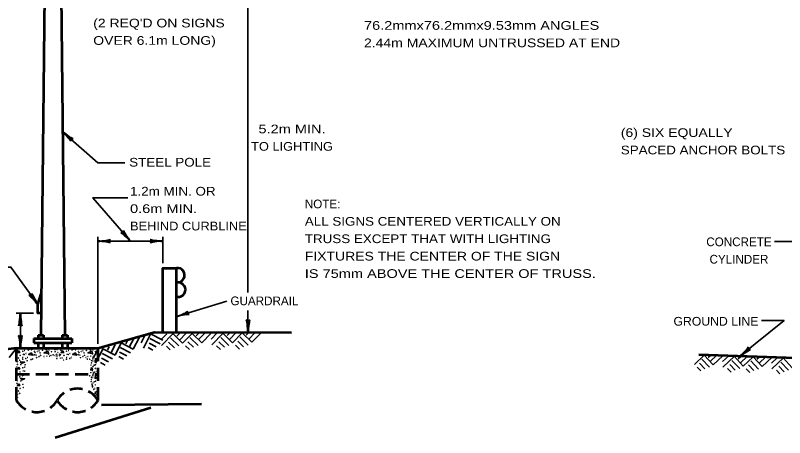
# Model space of a CAD drawing. Extents: x -31 to 824, y -13 to 531.
# Drawn here: x 91.3 to 303.3, y 278.2 to 394.6 of the extents above; entities that cross this region are included whole.
import ezdxf
from ezdxf.enums import TextEntityAlignment as Align

# ---------------------------------------------------------------- set-up
doc = ezdxf.new("R2010")
doc.units = 0
doc.header["$LTSCALE"] = 1.2
doc.linetypes.add('MEDIUM_DASHED', pattern=[4.5, 3, -1.5])
doc.layers.add('1', color=7, linetype='Continuous', lineweight=35)

msp = doc.modelspace()

# ---------------------------------------------------------------- linework, layer by layer
at = {"layer": '1', "lineweight": 53}
for p, q in [((99.754, 448.994), (98.27, 306.494)), ((103.648, 423.794), (104.87, 306.494)), ((135.713, 307.45), (135.713, 324.988)), ((96.32, 305.594), (106.82, 305.594)), ((96.32, 305.594), (96.32, 304.394)), ((97.52, 306.494), (99.02, 306.494)), ((97.52, 306.494), (97.52, 305.594)), ((99.02, 306.494), (99.02, 305.594)), ((104.12, 306.494), (105.62, 306.494)), ((104.12, 306.494), (104.12, 305.594)), ((105.62, 306.494), (105.62, 305.594)), ((106.82, 305.594), (106.82, 304.394)), ((96.32, 304.394), (106.82, 304.394)), ((97.52, 304.394), (97.52, 302.894)), ((99.02, 304.394), (99.02, 302.894)), ((104.12, 304.394), (104.12, 302.894)), ((105.62, 304.394), (105.62, 302.894)), ((91.52, 302.894), (67.699, 299.97)), ((91.52, 302.894), (114.02, 302.894)), ((313.283, 299.881), (279.704, 301.053)), ((102.244, 278.229), (128.57, 286.517)), ((114.96, 287.265), (142.559, 287.541))]:
    msp.add_line(p, q, dxfattribs=at)
at = {"layer": '1'}
for p, q in [((155.379, 414.794), (155.379, 318.241)), ((114.02, 304.094), (114.02, 333.598)), ((131.906, 326.282), (131.906, 333.598)), ((131.906, 332.398), (114.02, 332.398)), ((308.076, 332.307), (300.562, 332.307)), ((135.714, 311.612), (149.533, 315.843)), ((96.232, 312.494), (91.432, 312.494)), ((92.632, 312.494), (92.632, 302.894)), ((155.379, 313.304), (155.379, 307.252)), ((125.447, 305.91), (123.739, 302.633)), ((126.985, 306.394), (125.931, 304.373)), ((128.638, 306.915), (126.547, 302.902)), ((128.315, 305.584), (131.156, 304.123)), ((128.522, 306.878), (131.892, 305.123)), ((133.022, 306.883), (131.426, 305.255)), ((134.756, 306.9), (131.588, 303.669)), ((134.059, 305.721), (136.353, 303.496)), ((134.634, 306.899), (137.347, 304.239)), ((136.49, 306.917), (135.813, 306.202)), ((138.248, 306.935), (136.58, 305.233)), ((139.982, 306.952), (137.347, 304.239)), ((139.359, 305.847), (141.628, 303.622)), ((139.982, 306.952), (142.622, 304.365)), ((141.716, 306.97), (141.088, 306.328)), ((143.475, 306.987), (141.879, 305.359)), ((145.209, 307.004), (142.622, 304.365)), ((146.821, 307.021), (145.225, 305.393)), ((148.555, 307.038), (145.388, 303.806)), ((147.859, 305.858), (150.152, 303.634)), ((148.433, 307.036), (151.146, 304.377)), ((150.289, 307.055), (149.612, 306.34)), ((152.048, 307.073), (150.379, 305.371)), ((153.782, 307.09), (151.146, 304.377)), ((153.158, 305.985), (155.427, 303.76)), ((153.782, 307.09), (156.421, 304.503)), ((155.516, 307.107), (154.887, 306.466)), ((157.275, 307.125), (155.679, 305.497)), ((159.009, 307.142), (156.421, 304.503)), ((117.13, 303.292), (116.69, 302.411)), ((118.807, 303.82), (117.705, 301.706)), ((120.461, 304.341), (118.728, 300.979)), ((120.461, 304.341), (123.739, 302.633)), ((122.115, 304.862), (121.7, 304.065)), ((123.793, 305.39), (122.739, 303.368)), ((128.131, 304.297), (130.091, 303.276)), ((132.91, 303.413), (133.97, 302.398)), ((133.509, 304.543), (135.088, 302.995)), ((138.185, 303.539), (139.245, 302.499)), ((138.808, 304.669), (140.387, 303.121)), ((146.709, 303.551), (147.77, 302.536)), ((147.308, 304.68), (148.887, 303.133)), ((151.984, 303.677), (153.044, 302.637)), ((152.608, 304.807), (154.186, 303.259)), ((91.546, 302.855), (89.561, 300.313)), ((113.821, 302.25), (112.768, 300.229)), ((115.475, 302.771), (113.384, 298.759)), ((115.152, 301.44), (117.993, 299.979)), ((115.359, 302.735), (118.728, 300.979)), ((120.002, 301.815), (121.962, 300.793)), ((120.185, 303.102), (123.004, 301.633)), ((127.886, 303.042), (129.196, 302.379)), ((113.437, 300.082), (114.02, 299.749)), ((114.968, 300.153), (116.928, 299.132)), ((119.733, 300.552), (121.05, 299.866)), ((281.165, 300.954), (278.459, 298.407)), ((280.504, 299.897), (282.634, 297.613)), ((281.165, 300.954), (283.642, 298.298)), ((282.868, 300.895), (282.223, 300.293)), ((284.595, 300.834), (282.957, 299.307)), ((286.298, 300.775), (283.642, 298.298)), ((287.833, 300.721), (286.195, 299.193)), ((289.536, 300.662), (286.284, 297.629)), ((288.8, 299.535), (290.954, 297.25)), ((289.416, 300.666), (291.963, 297.935)), ((291.239, 300.602), (290.543, 299.93)), ((292.966, 300.542), (291.253, 298.945)), ((294.669, 300.483), (291.963, 297.935)), ((294.008, 299.425), (296.137, 297.141)), ((294.669, 300.483), (297.146, 297.826)), ((296.372, 300.423), (295.727, 299.821)), ((298.099, 300.363), (296.461, 298.835)), ((299.802, 300.303), (297.146, 297.826)), ((301.337, 300.25), (299.699, 298.722)), ((303.04, 300.19), (299.788, 297.158)), ((302.304, 299.063), (304.458, 296.779)), ((302.92, 300.194), (305.466, 297.464)), ((112.381, 297.49), (111.972, 297.325)), ((114.723, 298.898), (116.033, 298.235)), ((279.25, 297.683), (280.245, 296.615)), ((279.912, 298.764), (281.394, 297.176)), ((287.57, 297.32), (288.567, 296.277)), ((288.209, 298.403), (289.69, 296.814)), ((292.754, 297.211), (293.749, 296.144)), ((293.416, 298.293), (294.897, 296.704)), ((301.712, 297.931), (303.194, 296.343)), ((113.437, 295.522), (114.02, 295.189)), ((301.074, 296.849), (302.07, 295.805)), ((112.381, 292.93), (112.266, 292.884)), ((113.293, 290.314), (113.389, 290.986)), ((113.437, 290.962), (114.02, 290.629)), ((114.02, 290.357), (113.397, 290.053))]:
    msp.add_line(p, q, dxfattribs=at)
at = {"layer": '1', "linetype": 'MEDIUM_DASHED', "lineweight": 53}
for p, q in [((91.52, 288.494), (91.52, 302.894)), ((114.02, 302.894), (114.02, 288.494)), ((91.52, 295.694), (114.02, 295.694))]:
    msp.add_line(p, q, dxfattribs=at)
at = {"layer": '1'}
for points in [[(104.286, 362.553), (114.032, 353.974), (121.448, 353.974)], [(122.963, 332.398), (112.587, 344.337), (122.273, 344.337)], [(97.432, 314.894), (90.039, 325.254), (84.052, 325.254)], [(290.986, 300.659), (303.198, 310.495), (296.999, 310.495)], [(92.221, 302.218), (91.765, 301.738), (92.461, 301.69), (92.221, 302.17)], [(95.701, 301.594), (94.909, 301.162), (96.085, 300.946), (95.653, 301.618)], [(100.285, 302.05), (99.157, 301.594), (100.405, 301.45), (100.285, 302.002)], [(104.317, 302.218), (103.861, 301.738), (104.557, 301.69), (104.317, 302.17)], [(107.797, 301.594), (107.005, 301.162), (108.181, 300.946), (107.749, 301.618)], [(112.381, 302.05), (111.253, 301.594), (112.501, 301.45), (112.381, 302.002)], [(114.02, 299.477), (113.245, 299.098), (113.389, 300.106)], [(92.221, 297.658), (91.765, 297.178), (92.461, 297.13), (92.221, 297.61)], [(111.895, 296.96), (112.501, 296.89), (112.381, 297.442)], [(114.02, 294.917), (113.245, 294.538), (113.389, 295.546)], [(92.221, 293.098), (91.765, 292.618), (92.461, 292.57), (92.221, 293.05)], [(112.486, 292.332), (112.501, 292.33), (112.381, 292.882)]]:
    msp.add_lwpolyline(points, dxfattribs=at)
at = {"layer": '1', "lineweight": 53}
for points in [[(131.906, 307.302), (131.906, 324.988), (135.713, 324.988)], [(98.332, 312.494), (97.432, 312.494), (97.432, 314.894), (98.388, 317.894)], [(114.02, 302.894), (129.616, 307.307), (167.386, 307.226)]]:
    msp.add_lwpolyline(points, dxfattribs=at)
at = {"layer": '1'}
for points in [[(92.557, 299.146), (93.805, 299.002), (92.989, 298.714)], [(92.557, 294.586), (93.805, 294.442), (92.989, 294.154)]]:
    msp.add_lwpolyline(points, close=True, dxfattribs=at)
for centre in [(91.691, 302.303), (93.298, 302.048), (93.425, 301.189), (93.838, 302.255), (93.838, 301.141), (94.22, 301.428), (94.808, 302.366), (95.286, 302.599), (95.763, 302.446), (96.431, 302.79), (96.51, 301.969), (96.701, 301.714), (97.321, 301.969), (97.798, 302.16), (97.91, 302.79), (98.069, 301.603), (98.132, 301.603), (98.737, 302.287), (99.802, 302.398), (100.057, 302.774), (100.438, 301.284), (100.566, 302.35), (100.9, 302.742), (101.202, 301.905), (102.156, 302.462), (102.172, 302.663), (102.204, 301.921), (102.617, 301.205), (102.76, 302.525), (103.015, 301.698), (103.349, 302.679), (103.444, 301.221), (103.787, 302.303), (105.394, 302.048), (105.521, 301.189), (105.934, 302.255), (105.934, 301.141), (106.316, 301.428), (106.904, 302.366), (107.382, 302.599), (107.859, 302.446), (108.527, 302.79), (108.606, 301.969), (108.797, 301.714), (109.417, 301.969), (109.894, 302.16), (110.006, 302.79), (110.165, 301.603), (110.228, 301.603), (110.833, 302.287), (111.898, 302.398), (112.153, 302.774), (112.534, 301.284), (112.662, 302.35), (112.996, 302.742), (113.298, 301.905), (91.555, 300.123), (91.628, 301.125), (91.803, 299.169), (92.057, 300.187), (92.455, 299.566), (92.566, 300.919), (93.266, 299.837), (93.329, 300.314), (94.156, 300.06), (94.49, 299.439), (94.633, 300.314), (95.54, 299.709), (96.033, 299.916), (96.51, 301.078), (96.971, 300.966), (97.114, 300.282), (97.767, 300.569), (98.212, 300.903), (99.182, 300.585), (99.961, 300.696), (100.725, 300.68), (101.059, 300.887), (101.695, 301.03), (102.236, 300.855), (102.681, 300.06), (102.744, 300.728), (103.46, 300.839), (103.651, 300.123), (103.724, 301.125), (104.153, 300.187), (104.662, 300.919), (105.362, 299.837), (105.425, 300.314), (106.252, 300.06), (106.729, 300.314), (108.606, 301.078), (109.067, 300.966), (109.21, 300.282), (109.863, 300.569), (110.308, 300.903), (110.785, 300.314), (111.119, 299.869), (111.278, 300.585), (111.739, 299.837), (112.057, 300.696), (112.248, 299.439), (112.598, 299.36), (112.614, 299.932), (112.693, 300.298), (112.821, 300.68), (113.155, 300.887), (113.791, 301.03), (91.691, 297.743), (91.803, 298.453), (92.773, 298.405), (93.298, 297.488), (93.838, 297.695), (93.966, 298.31), (112.153, 298.214), (112.264, 298.819), (112.662, 297.79), (112.996, 298.182), (113.298, 297.345), (113.33, 298.325), (91.555, 295.563), (91.628, 296.565), (92.057, 295.627), (92.455, 295.006), (92.566, 296.359), (93.266, 295.277), (93.329, 295.754), (93.425, 296.629), (93.838, 296.581), (111.739, 295.277), (112.057, 296.136), (112.248, 294.879), (112.534, 296.724), (112.598, 294.8), (112.614, 295.372), (112.693, 295.738), (112.821, 296.12), (113.155, 296.327), (113.791, 296.47), (91.691, 293.183), (91.803, 294.609), (91.803, 293.893), (92.773, 293.845), (93.298, 292.928), (112.153, 293.654), (112.264, 294.259), (112.662, 293.23), (112.996, 293.622), (113.298, 292.785), (113.33, 293.765), (91.555, 291.003), (91.628, 292.005), (92.057, 291.067), (92.566, 291.799), (93.425, 292.069), (113.155, 291.767), (113.791, 291.91), (91.803, 290.049), (91.803, 289.333), (92.455, 290.446)]:
    msp.add_circle(centre, 0.0318, dxfattribs=at)
at = {"layer": '1', "lineweight": 53}
for centre, start in [((135.928, 322.996), 269.90797), ((136.14, 319), 265.7864)]:
    msp.add_arc(centre, 2.004, start, 96.15193, dxfattribs=at)
at = {"layer": '1'}
for centre, start, end in [((93.966, 302.87), 128.57089, 51.42911), ((101.234, 302.885), 163.53529, 16.46471), ((106.062, 302.87), 128.57089, 51.42911), ((113.33, 302.885), 163.53529, 16.46471), ((91.531, 299.15), 248.848, 111.152), ((104.551, 299.566), 354.03394, 177.83848), ((91.531, 294.59), 248.848, 111.152), ((112.534, 292.164), 324.97238, 78.59543), ((112.821, 291.56), 242.36511, 161.20271), ((91.531, 290.03), 248.848, 111.152)]:
    msp.add_arc(centre, 0.0318, start, end, dxfattribs=at)
at = {"layer": '1', "linetype": 'MEDIUM_DASHED', "lineweight": 53}
for centre, start, end in [((108.395, 285.222), 30.19173, 149.80827), ((97.145, 291.767), 210.19173, 329.80827), ((108.395, 291.767), 210.19173, 329.80827)]:
    msp.add_arc(centre, 6.508, start, end, dxfattribs=at)
at = {"layer": '1', "lineweight": 40}
for centre, major_axis, ratio, start_param, end_param in [((105.127, 361.474), (1.443, -1.551), 0.07063, 6.2823074, 8.5597026), ((105.488, 361.937), (-1.732, 1.275), 0.122415, 0.8963533, 3.1415927), ((122.273, 333.579), (1.223, -1.729), 0.07063, 3.1407148, 5.41811), ((121.854, 333.169), (1.547, -1.495), 0.122415, 0.8963533, 3.1415927), ((115.364, 332.144), (-2.108, 0.211), 0.07063, 3.1407148, 5.41811), ((115.364, 332.144), (-2.108, 0.211), 0.07063, 3.1407148, 5.41811), ((115.329, 332.729), (-2.143, -0.187), 0.122415, 0.8963533, 3.1415927), ((115.329, 332.729), (-2.143, -0.187), 0.122415, 0.8963533, 3.1415927), ((130.597, 332.066), (2.143, 0.187), 0.122415, 0.8963533, 3.1415927), ((130.561, 332.652), (2.108, -0.211), 0.07063, 3.1407148, 5.41811), ((96.402, 315.767), (1.397, -1.635), 0.122415, 0.8963533, 3.1415927), ((96.858, 316.136), (-1.053, 1.838), 0.07063, 6.2823074, 8.5597026), ((92.378, 311.149), (0.211, 2.108), 0.07063, 3.1407148, 5.41811), ((92.378, 311.149), (0.211, 2.108), 0.07063, 3.1407148, 5.41811), ((92.964, 311.185), (-0.187, 2.143), 0.122415, 0.8963533, 3.1415927), ((92.964, 311.185), (-0.187, 2.143), 0.122415, 0.8963533, 3.1415927), ((136.868, 312.312), (-1.994, -0.807), 0.122415, 0.8963533, 3.1415927), ((137.074, 311.763), (-2.077, -0.416), 0.07063, 3.1407148, 5.41811), ((155.057, 308.572), (0.187, -2.143), 0.122415, 0.8963533, 3.1415927), ((155.643, 308.607), (-0.211, -2.108), 0.07063, 3.1407148, 5.41811), ((92.301, 304.204), (0.187, -2.143), 0.122415, 0.8963533, 3.1415927), ((92.886, 304.239), (-0.211, -2.108), 0.07063, 3.1407148, 5.41811), ((291.798, 301.739), (-1.551, -1.49), 0.122415, 0.8963533, 3.1415927), ((292.193, 301.305), (1.774, 1.158), 0.07063, 6.2823074, 8.5597026)]:
    msp.add_ellipse(centre, major_axis=major_axis, ratio=ratio, start_param=start_param, end_param=end_param, dxfattribs=at)

# ---------------------------------------------------------------- texts
at = {"layer": '1'}
for s, width, p in [("(2 REQ'D ON SIGNS", 1.2, (112.717, 391.321)), ('76.2mmx76.2mmx9.53mm ANGLES', 1.25, (187.375, 390.663)), ('OVER 6.1m LONG)', 1.2, (112.717, 386.521)), ('2.44m MAXIMUM UNTRUSSED AT END', 1.2, (187.375, 385.863)), ('(6) SIX EQUALLY', 1.2, (258.186, 361.114)), ('SPACED ANCHOR BOLTS', 1.15, (258.186, 356.314)), ('STEEL POLE', 1.15, (122.639, 352.954)), ('1.2m MIN. OR', 1.15, (122.87, 344.956)), ('0.6m MIN.', 1.25, (122.87, 340.156)), ('BEHIND CURBLINE', 1.1, (122.87, 335.356)), ('ALL SIGNS CENTERED VERTICALLY ON', 1.15, (171.056, 336.654)), ('TRUSS EXCEPT THAT WITH LIGHTING', 1.15, (171.056, 331.854)), ('FIXTURES THE CENTER OF THE SIGN', 1.2, (171.056, 327.054)), ('IS 75mm ABOVE THE CENTER OF TRUSS.', 1.25, (171.056, 322.254)), ('GROUND LINE', 1.05, (272.705, 309.101))]:
    msp.add_text(s, height=2.4, dxfattribs=dict(at, width=width)).set_placement(p)
for s, width, p in [('5.2m MIN.', 1.25, (167.528, 362.119)), ('TO LIGHTING', 1.1, (167.528, 357.319))]:
    msp.add_text(s, height=2.4, dxfattribs=dict(at, width=width)).set_placement(p, align=Align.CENTER)
for s, p in [('NOTE:', (171.056, 341.454)), ('GUARDRAIL', (150.559, 314.727))]:
    msp.add_text(s, height=2.4, dxfattribs=at).set_placement(p)
for s, p in [('CONCRETE', (290.76, 331.01)), ('CYLINDER', (290.76, 326.21))]:
    msp.add_text(s, height=2.4, dxfattribs=at).set_placement(p, align=Align.CENTER)

doc.saveas('drawing.dxf')
